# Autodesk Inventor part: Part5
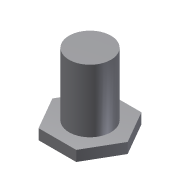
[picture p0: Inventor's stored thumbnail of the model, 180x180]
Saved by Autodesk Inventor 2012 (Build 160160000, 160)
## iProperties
Created: 2008-05
Part Number: Part5
Document SubType Name: Modeling
Designer: CADCIM
Density: 1 g/cm^3
Material: Default
Author: CADCIM
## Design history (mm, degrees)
sketch "Sketch1"
  geometry: C1 r 2 at (-7.12, 11.618)
  constraints: 1 centre point
  dimensions: "d2" = 4 diameter of C1
extrude "Extrusion1" new body sketch "Sketch1" distance "d0" = 6; taper "d1" = 0 deg
sketch "Sketch2"
  geometry: L1 (-3.598, 0)-(-1.799, 3.116); L2 (-1.799, 3.116)-(1.799, 3.116); L3 (1.799, 3.116)-(3.598, 0); L4 (3.598, 0)-(1.799, -3.116); L5 (1.799, -3.116)-(-1.799, -3.116); L6 (-1.799, -3.116)-(-3.598, 0); C1 r 2 at (0, 0) reference; 1 further point
  constraints: 12 end point, 1 coincident, 13 other
extrude "Extrusion2" join sketch "Sketch2" distance "d3" = 1; taper "d4" = 0 deg
body "Solid1"
